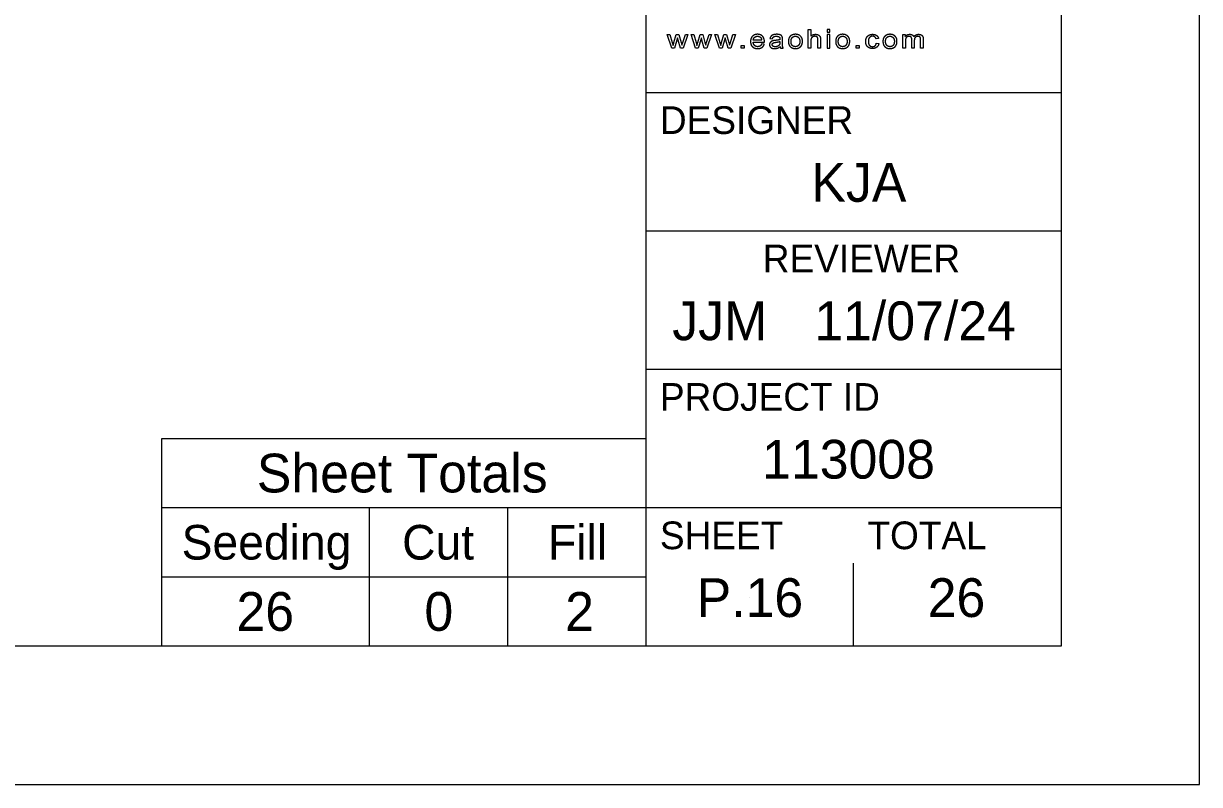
# Model space of a CAD drawing. Extents: x -34 to 34, y -215 to 22.
# Drawn here: x 29.75 to 34, y 0 to 2.749 of the extents above; entities that cross this region are included whole.
import ezdxf

# ---------------------------------------------------------------- set-up
doc = ezdxf.new("R2010")
doc.units = 0
for name, color, linetype in [('BR_X_SV_Deck_Top_Text', 7, 'Continuous'), ('Default', 7, 'Continuous'), ('SV_X_Text_Comment', 7, 'Continuous'), ('SV_X_Text_Elevation', 7, 'Continuous'), ('UT_X_Gas_Cells', 7, 'Continuous')]:
    doc.layers.add(name, color=color, linetype=linetype)

msp = doc.modelspace()

# ---------------------------------------------------------------- linework, layer by layer
at = {"layer": 'BR_X_SV_Deck_Top_Text'}
for p, q in [((32, 0.5), (32, 21.5)), ((32, 2.5), (33.5, 2.5)), ((32, 2), (33.5, 2)), ((32, 1.5), (33.5, 1.5)), ((32, 1), (33.5, 1))]:
    msp.add_line(p, q, dxfattribs=at)
msp.add_lwpolyline([(1.5, 21.5), (33.5, 21.5), (33.5, 0.5), (1.5, 0.5)], close=True, dxfattribs=at)
at = {"layer": 'SV_X_Text_Comment'}
msp.add_lwpolyline([(0, 0), (34, 0), (34, 22), (0, 22)], close=True, dxfattribs=at)
at = {"layer": 'SV_X_Text_Elevation'}
for p, q in [((30.25, 0.5), (30.25, 1.25)), ((30.25, 1.25), (32, 1.25)), ((30.25, 1), (32, 1)), ((31, 0.5), (31, 1)), ((31.5, 0.5), (31.5, 1)), ((32.75, 0.5), (32.75, 0.8)), ((30.25, 0.75), (32, 0.75)), ((32.375, 0.675), (32.375, 0.675)), ((30.6316, 0.625), (30.6316, 0.625)), ((31.2545, 0.625), (31.2545, 0.625)), ((31.7599, 0.625), (31.7599, 0.625))]:
    msp.add_line(p, q, dxfattribs=at)
at = {"layer": 'UT_X_Gas_Cells'}
for p, q in [((32.387, 2.6821), (32.4274, 2.6821)), ((32.4178, 2.6889), (32.3875, 2.6889)), ((32.4477, 2.6948), (32.4567, 2.6937)), ((32.4838, 2.6843), (32.4838, 2.6812)), ((32.4931, 2.6802), (32.4931, 2.6913)), ((32.5143, 2.6842), (32.5143, 2.6842)), ((32.5238, 2.6842), (32.5238, 2.6842)), ((32.6852, 2.6842), (32.6852, 2.6842)), ((32.6946, 2.6842), (32.6946, 2.6842)), ((32.8402, 2.6944), (32.8313, 2.6931)), ((32.8321, 2.6776), (32.8411, 2.6765)), ((32.856, 2.6842), (32.856, 2.6842)), ((32.8655, 2.6842), (32.8655, 2.6842)), ((32.4272, 2.6744), (32.4177, 2.6755)), ((32.4846, 2.6656), (32.4846, 2.6656)), ((32.4864, 2.6596), (32.496, 2.6596))]:
    msp.add_line(p, q, dxfattribs=at)
for points in [[(32.5955, 2.6865), (32.5955, 2.6596), (32.5863, 2.6596), (32.5863, 2.7276), (32.5955, 2.7276), (32.5955, 2.7032)], [(32.1007, 2.68), (32.1093, 2.7089), (32.1188, 2.7089), (32.1269, 2.6802), (32.1295, 2.6708), (32.1327, 2.6804), (32.142, 2.7089), (32.1509, 2.7089), (32.1339, 2.6596), (32.1244, 2.6596), (32.1158, 2.6891), (32.1137, 2.6975), (32.1027, 2.6596), (32.0931, 2.6596), (32.0766, 2.7089), (32.0861, 2.7089), (32.0947, 2.6804), (32.0979, 2.6698)], [(32.1867, 2.68), (32.1953, 2.7089), (32.2048, 2.7089), (32.2129, 2.6802), (32.2155, 2.6708), (32.2186, 2.6804), (32.228, 2.7089), (32.2369, 2.7089), (32.2199, 2.6596), (32.2104, 2.6596), (32.2018, 2.6891), (32.1997, 2.6975), (32.1886, 2.6596), (32.179, 2.6596), (32.1625, 2.7089), (32.172, 2.7089), (32.1807, 2.6804), (32.1838, 2.6698)], [(32.2726, 2.68), (32.2813, 2.7089), (32.2907, 2.7089), (32.2988, 2.6802), (32.3015, 2.6708), (32.3046, 2.6804), (32.3139, 2.7089), (32.3229, 2.7089), (32.3059, 2.6596), (32.2964, 2.6596), (32.2878, 2.6891), (32.2856, 2.6975), (32.2746, 2.6596), (32.265, 2.6596), (32.2485, 2.7089), (32.258, 2.7089), (32.2666, 2.6804), (32.2698, 2.6698)], [(32.6305, 2.6908), (32.6305, 2.6596), (32.6213, 2.6596), (32.6213, 2.6908)], [(32.9372, 2.6851), (32.9372, 2.6596), (32.928, 2.6596), (32.928, 2.7089), (32.9362, 2.7089), (32.9362, 2.7019)], [(32.9694, 2.6882), (32.9694, 2.6596), (32.9602, 2.6596), (32.9602, 2.6916)], [(33.0015, 2.6934), (33.0015, 2.6596), (32.9923, 2.6596), (32.9923, 2.6906)]]:
    msp.add_lwpolyline(points, dxfattribs=at)
for points in [[(32.655, 2.718), (32.6642, 2.718), (32.6642, 2.7276), (32.655, 2.7276)], [(32.655, 2.6596), (32.6642, 2.6596), (32.6642, 2.7089), (32.655, 2.7089)], [(32.3437, 2.6596), (32.3437, 2.669), (32.3541, 2.669), (32.3541, 2.6596)], [(32.7597, 2.6596), (32.7597, 2.669), (32.7702, 2.669), (32.7702, 2.6596)]]:
    msp.add_lwpolyline(points, close=True, dxfattribs=at)
for points in [[(32.0979, 2.6698), (32.0981, 2.6706), (32.1007, 2.68)], [(32.1838, 2.6698), (32.184, 2.6706), (32.1867, 2.68)], [(32.2698, 2.6698), (32.27, 2.6706), (32.2726, 2.68)], [(32.3846, 2.7031), (32.3775, 2.6962), (32.3775, 2.6838)], [(32.3775, 2.6838), (32.3775, 2.6718), (32.3845, 2.6651)], [(32.4028, 2.71), (32.3916, 2.71), (32.3846, 2.7031)], [(32.3921, 2.6696), (32.3875, 2.6739), (32.387, 2.6821)], [(32.3875, 2.6889), (32.388, 2.6954), (32.3923, 2.6992)], [(32.3923, 2.6992), (32.3966, 2.7031), (32.4029, 2.7031)], [(32.4206, 2.7032), (32.4137, 2.71), (32.4028, 2.71)], [(32.4029, 2.7031), (32.4099, 2.7031), (32.4143, 2.6983)], [(32.4143, 2.6983), (32.4172, 2.6951), (32.4178, 2.6889)], [(32.4275, 2.6843), (32.4275, 2.6965), (32.4206, 2.7032)], [(32.4274, 2.6821), (32.4275, 2.6835), (32.4275, 2.6843)], [(32.4479, 2.6792), (32.4461, 2.6762), (32.4461, 2.6726)], [(32.4517, 2.7032), (32.4489, 2.7), (32.4477, 2.6948)], [(32.4526, 2.684), (32.4497, 2.6822), (32.4479, 2.6792)], [(32.4598, 2.7082), (32.4545, 2.7065), (32.4517, 2.7032)], [(32.4592, 2.6867), (32.4555, 2.6858), (32.4526, 2.684)], [(32.4567, 2.6937), (32.4581, 2.6989), (32.4612, 2.701)], [(32.4571, 2.6768), (32.4584, 2.6785), (32.4608, 2.6795)], [(32.4674, 2.688), (32.4619, 2.6873), (32.4592, 2.6867)], [(32.4721, 2.71), (32.4651, 2.71), (32.4598, 2.7082)], [(32.4608, 2.6795), (32.4631, 2.6804), (32.4688, 2.6811)], [(32.4612, 2.701), (32.4643, 2.7031), (32.4708, 2.7031)], [(32.4838, 2.6908), (32.4785, 2.6892), (32.4674, 2.688)], [(32.4688, 2.6811), (32.4788, 2.6824), (32.4838, 2.6843)], [(32.4708, 2.7031), (32.4777, 2.7031), (32.4812, 2.7002)], [(32.4834, 2.7085), (32.479, 2.71), (32.4721, 2.71)], [(32.4812, 2.7002), (32.4838, 2.6981), (32.4838, 2.693)], [(32.4838, 2.6812), (32.4838, 2.6757), (32.4823, 2.6729)], [(32.4897, 2.7047), (32.4877, 2.707), (32.4834, 2.7085)], [(32.4838, 2.693), (32.4838, 2.6925), (32.4838, 2.6908)], [(32.4926, 2.699), (32.4918, 2.7025), (32.4897, 2.7047)], [(32.4931, 2.6913), (32.4931, 2.6969), (32.4926, 2.699)], [(32.4936, 2.6655), (32.4931, 2.6686), (32.4931, 2.6802)], [(32.5227, 2.7045), (32.5143, 2.6979), (32.5143, 2.6842)], [(32.5143, 2.6842), (32.5143, 2.6717), (32.5214, 2.6651)], [(32.5398, 2.71), (32.5297, 2.71), (32.5227, 2.7045)], [(32.5238, 2.6842), (32.5238, 2.6937), (32.5283, 2.6984)], [(32.5283, 2.67), (32.5238, 2.6747), (32.5238, 2.6842)], [(32.5283, 2.6984), (32.5329, 2.7031), (32.5398, 2.7031)], [(32.558, 2.7033), (32.5509, 2.71), (32.5398, 2.71)], [(32.5398, 2.7031), (32.5465, 2.7031), (32.5511, 2.6983)], [(32.5511, 2.6983), (32.5556, 2.6936), (32.5556, 2.6845)], [(32.5556, 2.6845), (32.5556, 2.6748), (32.5511, 2.6701)], [(32.5651, 2.6849), (32.5651, 2.6966), (32.558, 2.7033)], [(32.562, 2.67), (32.5651, 2.6754), (32.5651, 2.6849)], [(32.5955, 2.7032), (32.602, 2.71), (32.6118, 2.71)], [(32.5971, 2.6956), (32.5955, 2.6923), (32.5955, 2.6865)], [(32.6022, 2.7008), (32.5986, 2.6989), (32.5971, 2.6956)], [(32.6099, 2.7028), (32.6058, 2.7028), (32.6022, 2.7008)], [(32.6183, 2.6999), (32.6153, 2.7028), (32.6099, 2.7028)], [(32.6118, 2.71), (32.6178, 2.71), (32.6222, 2.7078)], [(32.6213, 2.6908), (32.6213, 2.697), (32.6183, 2.6999)], [(32.6222, 2.7078), (32.6267, 2.7056), (32.6286, 2.7018)], [(32.6286, 2.7018), (32.6305, 2.698), (32.6305, 2.6908)], [(32.6935, 2.7045), (32.6852, 2.6979), (32.6852, 2.6842)], [(32.6852, 2.6842), (32.6852, 2.6717), (32.6922, 2.6651)], [(32.7106, 2.71), (32.7005, 2.71), (32.6935, 2.7045)], [(32.6946, 2.6842), (32.6946, 2.6937), (32.6992, 2.6984)], [(32.6992, 2.67), (32.6946, 2.6747), (32.6946, 2.6842)], [(32.6992, 2.6984), (32.7037, 2.7031), (32.7106, 2.7031)], [(32.7288, 2.7033), (32.7218, 2.71), (32.7106, 2.71)], [(32.7106, 2.7031), (32.7174, 2.7031), (32.7219, 2.6983)], [(32.7219, 2.6983), (32.7265, 2.6936), (32.7265, 2.6845)], [(32.7265, 2.6845), (32.7265, 2.6748), (32.7219, 2.6701)], [(32.7359, 2.6849), (32.7359, 2.6966), (32.7288, 2.7033)], [(32.7328, 2.67), (32.7359, 2.6754), (32.7359, 2.6849)], [(32.7939, 2.684), (32.7939, 2.692), (32.7968, 2.698)], [(32.8006, 2.6651), (32.7939, 2.6717), (32.7939, 2.684)], [(32.7968, 2.698), (32.7997, 2.704), (32.8056, 2.707)], [(32.8077, 2.6986), (32.8033, 2.6941), (32.8033, 2.6843)], [(32.8033, 2.6843), (32.8033, 2.6743), (32.8075, 2.6698)], [(32.8056, 2.707), (32.8116, 2.71), (32.8186, 2.71)], [(32.8189, 2.7031), (32.812, 2.7031), (32.8077, 2.6986)], [(32.8186, 2.71), (32.8274, 2.71), (32.833, 2.7059)], [(32.8268, 2.7006), (32.8235, 2.7031), (32.8189, 2.7031)], [(32.8313, 2.6931), (32.83, 2.6981), (32.8268, 2.7006)], [(32.8275, 2.6683), (32.8311, 2.6713), (32.8321, 2.6776)], [(32.833, 2.7059), (32.8387, 2.7018), (32.8402, 2.6944)], [(32.8644, 2.7045), (32.856, 2.6979), (32.856, 2.6842)], [(32.856, 2.6842), (32.856, 2.6717), (32.863, 2.6651)], [(32.8814, 2.71), (32.8714, 2.71), (32.8644, 2.7045)], [(32.8655, 2.6842), (32.8655, 2.6937), (32.87, 2.6984)], [(32.87, 2.67), (32.8655, 2.6747), (32.8655, 2.6842)], [(32.87, 2.6984), (32.8745, 2.7031), (32.8814, 2.7031)], [(32.8997, 2.7033), (32.8926, 2.71), (32.8814, 2.71)], [(32.8814, 2.7031), (32.8882, 2.7031), (32.8927, 2.6983)], [(32.8927, 2.6983), (32.8973, 2.6936), (32.8973, 2.6845)], [(32.8973, 2.6845), (32.8973, 2.6748), (32.8928, 2.6701)], [(32.9068, 2.6849), (32.9068, 2.6966), (32.8997, 2.7033)], [(32.9036, 2.67), (32.9068, 2.6754), (32.9068, 2.6849)], [(32.9362, 2.7019), (32.9388, 2.7055), (32.943, 2.7077)], [(32.9387, 2.6954), (32.9372, 2.6918), (32.9372, 2.6851)], [(32.9434, 2.7008), (32.9401, 2.699), (32.9387, 2.6954)], [(32.943, 2.7077), (32.9472, 2.71), (32.9527, 2.71)], [(32.9506, 2.7027), (32.9467, 2.7027), (32.9434, 2.7008)], [(32.958, 2.6999), (32.9557, 2.7027), (32.9506, 2.7027)], [(32.9527, 2.71), (32.9587, 2.71), (32.9625, 2.7077)], [(32.9602, 2.6916), (32.9602, 2.6971), (32.958, 2.6999)], [(32.9625, 2.7077), (32.9664, 2.7054), (32.968, 2.7013)], [(32.968, 2.7013), (32.9744, 2.71), (32.9847, 2.71)], [(32.9732, 2.6992), (32.9694, 2.6958), (32.9694, 2.6882)], [(32.9827, 2.7027), (32.977, 2.7027), (32.9732, 2.6992)], [(32.9882, 2.7014), (32.9858, 2.7027), (32.9827, 2.7027)], [(32.9847, 2.71), (32.9928, 2.71), (32.9972, 2.7059)], [(32.9914, 2.6978), (32.9905, 2.7), (32.9882, 2.7014)], [(32.9923, 2.6906), (32.9923, 2.6956), (32.9914, 2.6978)], [(32.9972, 2.7059), (33.0015, 2.7018), (33.0015, 2.6934)], [(32.3845, 2.6651), (32.3915, 2.6585), (32.4034, 2.6585)], [(32.4034, 2.6653), (32.3966, 2.6653), (32.3921, 2.6696)], [(32.412, 2.6677), (32.4085, 2.6653), (32.4034, 2.6653)], [(32.4034, 2.6585), (32.4128, 2.6585), (32.4189, 2.6626)], [(32.4177, 2.6755), (32.4156, 2.6702), (32.412, 2.6677)], [(32.4189, 2.6626), (32.4249, 2.6668), (32.4272, 2.6744)], [(32.4461, 2.6726), (32.4461, 2.6664), (32.4509, 2.6624)], [(32.4509, 2.6624), (32.4556, 2.6585), (32.4646, 2.6585)], [(32.4559, 2.6728), (32.4559, 2.675), (32.4571, 2.6768)], [(32.4586, 2.6672), (32.4559, 2.6695), (32.4559, 2.6728)], [(32.4668, 2.665), (32.4614, 2.665), (32.4586, 2.6672)], [(32.4646, 2.6585), (32.47, 2.6585), (32.4747, 2.6601)], [(32.4762, 2.6671), (32.4721, 2.665), (32.4668, 2.665)], [(32.4747, 2.6601), (32.4794, 2.6617), (32.4846, 2.6656)], [(32.4823, 2.6729), (32.4803, 2.6692), (32.4762, 2.6671)], [(32.4846, 2.6656), (32.485, 2.6622), (32.4864, 2.6596)], [(32.496, 2.6596), (32.4942, 2.6624), (32.4936, 2.6655)], [(32.5214, 2.6651), (32.5284, 2.6585), (32.5398, 2.6585)], [(32.5398, 2.6653), (32.5329, 2.6653), (32.5283, 2.67)], [(32.5511, 2.6701), (32.5466, 2.6653), (32.5398, 2.6653)], [(32.5398, 2.6585), (32.5468, 2.6585), (32.5528, 2.6615)], [(32.5528, 2.6615), (32.5588, 2.6645), (32.562, 2.67)], [(32.6922, 2.6651), (32.6992, 2.6585), (32.7106, 2.6585)], [(32.7106, 2.6653), (32.7037, 2.6653), (32.6992, 2.67)], [(32.7219, 2.6701), (32.7174, 2.6653), (32.7106, 2.6653)], [(32.7106, 2.6585), (32.7177, 2.6585), (32.7237, 2.6615)], [(32.7237, 2.6615), (32.7297, 2.6645), (32.7328, 2.67)], [(32.8185, 2.6585), (32.8074, 2.6585), (32.8006, 2.6651)], [(32.8075, 2.6698), (32.8117, 2.6653), (32.8185, 2.6653)], [(32.8185, 2.6653), (32.8239, 2.6653), (32.8275, 2.6683)], [(32.8335, 2.6633), (32.8274, 2.6585), (32.8185, 2.6585)], [(32.8411, 2.6765), (32.8396, 2.668), (32.8335, 2.6633)], [(32.863, 2.6651), (32.87, 2.6585), (32.8814, 2.6585)], [(32.8814, 2.6653), (32.8745, 2.6653), (32.87, 2.67)], [(32.8928, 2.6701), (32.8882, 2.6653), (32.8814, 2.6653)], [(32.8814, 2.6585), (32.8885, 2.6585), (32.8945, 2.6615)], [(32.8945, 2.6615), (32.9005, 2.6645), (32.9036, 2.67)]]:
    msp.add_open_spline(points, degree=2, dxfattribs=at)

# ---------------------------------------------------------------- texts
at = {"layer": 'Default'}
for s, p in [('26', (30.5196, 0.555)), ('0', (31.1989, 0.555)), ('2', (31.7076, 0.555))]:
    msp.add_text(s, height=0.14, dxfattribs=at).set_placement(p)
at = {"layer": 'SV_X_Text_Elevation'}
for s, height, p in [('DESIGNER', 0.1, (32.05, 2.35)), ('KJA', 0.14, (32.5975, 2.105)), ('REVIEWER', 0.1, (32.4218, 1.85)), ('JJM', 0.14, (32.0946, 1.605)), ('11/07/24', 0.14, (32.6078, 1.605)), ('PROJECT ID', 0.1, (32.05, 1.35)), ('113008', 0.14, (32.4193, 1.105)), ('Sheet Totals', 0.14, (30.5931, 1.055)), ('Seeding', 0.125, (30.3214, 0.8125)), ('Cut', 0.125, (31.1183, 0.8125)), ('Fill', 0.125, (31.6455, 0.8125)), ('SHEET', 0.1, (32.05, 0.85)), ('TOTAL', 0.1, (32.8, 0.85)), ('P.16', 0.14, (32.1827, 0.605)), ('26', 0.14, (33.0176, 0.605))]:
    msp.add_text(s, height=height, dxfattribs=at).set_placement(p)

doc.saveas('drawing.dxf')
